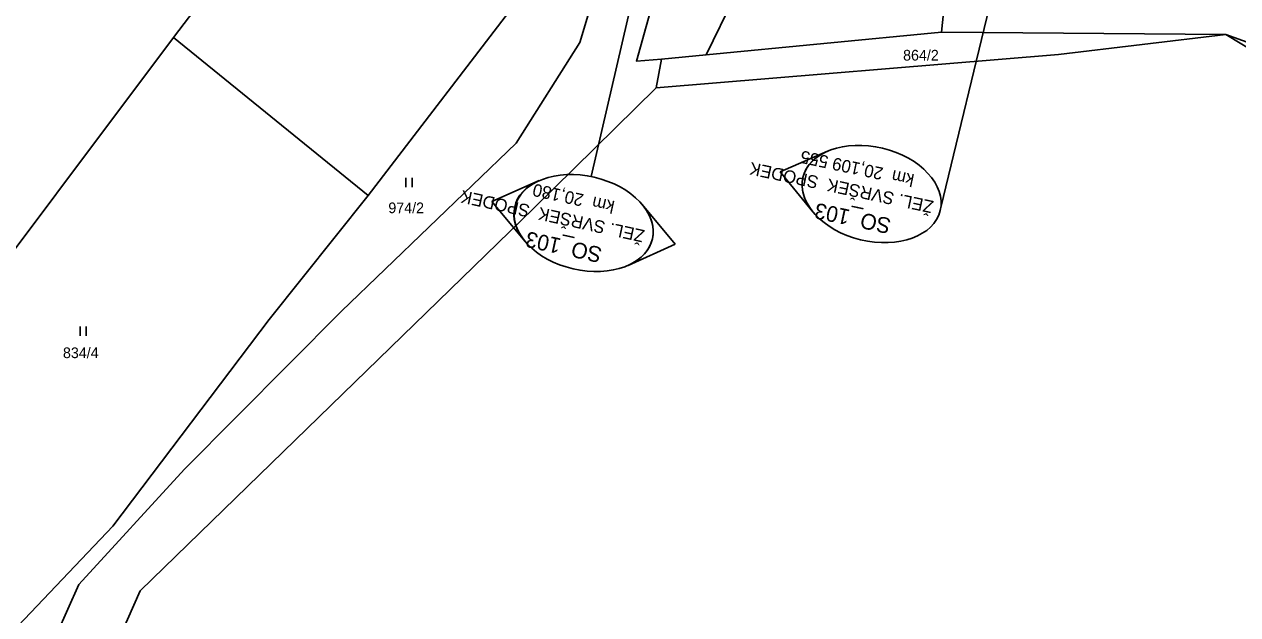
# Model space of a CAD drawing. Extents: x -7483133 to -743169, y -11317770 to -1127091.
# Drawn here: x -747701.7 to -747508.3, y -1131850 to -1131755.9 of the extents above; entities that cross this region are included whole.
import ezdxf

# ---------------------------------------------------------------- set-up
doc = ezdxf.new("R2010")
doc.units = 0
for name, color, linetype in [('_Násyp', 7, 'Continuous'), ('bublina_fialová_čára_tenká', 7, 'Continuous'), ('bublina_růžová_230_čára_tučná', 7, 'Continuous'), ('Hranice parcel', 7, 'Continuous'), ('Parcelní čísla', 7, 'Continuous'), ('Značky kultur', 7, 'Continuous')]:
    doc.layers.add(name, color=color, linetype=linetype)

msp = doc.modelspace()

# ---------------------------------------------------------------- linework, layer by layer
at = {"layer": 'bublina_fialová_čára_tenká'}
for p, q in [((-747611.38, -1131780.16), (-747594.17, -1131705.8)), ((-747555.65, -1131785.08), (-747539.65, -1131718.99))]:
    msp.add_line(p, q, dxfattribs=at)
at = {"layer": 'bublina_růžová_230_čára_tučná'}
for p, q in [((-747581.26, -1131779.44), (-747573.69, -1131776.14)), ((-747581.26, -1131779.44), (-747573.69, -1131776.14)), ((-747619.68, -1131780.79), (-747627.22, -1131784.15)), ((-747619.68, -1131780.79), (-747627.22, -1131784.15)), ((-747576.03, -1131785.82), (-747581.26, -1131779.44)), ((-747576.03, -1131785.82), (-747581.26, -1131779.44)), ((-747627.22, -1131784.15), (-747621.93, -1131790.49)), ((-747627.22, -1131784.15), (-747621.93, -1131790.49)), ((-747597.96, -1131790.97), (-747603.25, -1131784.63)), ((-747597.96, -1131790.97), (-747603.25, -1131784.63)), ((-747605.5, -1131794.33), (-747597.96, -1131790.97)), ((-747605.5, -1131794.33), (-747597.96, -1131790.97))]:
    msp.add_line(p, q, dxfattribs=at)
for centre, major_axis in [((-747566.68, -1131782.95), (10.94, -2.64)), ((-747612.57, -1131787.58), (-10.96, 2.54))]:
    msp.add_ellipse(centre, major_axis=major_axis, ratio=0.666667, dxfattribs=at)
for centre, major_axis in [((-747566.68, -1131782.95), (-10.94, 2.64)), ((-747612.6, -1131787.54), (-10.96, 2.54)), ((-747612.57, -1131787.58), (10.96, -2.54))]:
    msp.add_ellipse(centre, major_axis=major_axis, ratio=0.666473, start_param=5.557317, end_param=7.009053, dxfattribs=at)
at = {"layer": 'Hranice parcel'}
for p, q in [((-747635.51, -1131701.73), (-747677.94, -1131758.02)), ((-747551.8, -1131720.33), (-747555.53, -1131757.15)), ((-747646.92, -1131783.21), (-747603.39, -1131726.29)), ((-747593.06, -1131760.75), (-747588.32, -1131751.04)), ((-747555.53, -1131757.15), (-747593.06, -1131760.75)), ((-747555.53, -1131757.15), (-747510.21, -1131757.54)), ((-747677.94, -1131758.02), (-747646.92, -1131783.21)), ((-747600.14, -1131761.43), (-747601, -1131766.04)), ((-747593.06, -1131760.75), (-747600.14, -1131761.43))]:
    msp.add_line(p, q, dxfattribs=at)
for points in [[(-747600.14, -1131761.43), (-747604.15, -1131761.78), (-747597.33, -1131737.34), (-747594.14, -1131719.37), (-747592.13, -1131708.07)], [(-747603.39, -1131726.29), (-747613.18, -1131758.77), (-747623.35, -1131774.87), (-747651.15, -1131801.66), (-747676.19, -1131826.81), (-747693.02, -1131845.21), (-747696.56, -1131853.11), (-747694.42, -1131867.19)], [(-747510.21, -1131757.54), (-747536.87, -1131760.7), (-747601, -1131766.04)], [(-747510.21, -1131757.54), (-747496.95, -1131762.32), (-747474.01, -1131774.9), (-747459.79, -1131781.43), (-747448.86, -1131785.87)], [(-747340.05, -1131843.48), (-747375.12, -1131825.91), (-747485.07, -1131772.73), (-747510.21, -1131757.54)], [(-747677.94, -1131758.02), (-747715.35, -1131807.86), (-747754.13, -1131856.36)], [(-747601, -1131766.04), (-747620.58, -1131785.29), (-747683.25, -1131846.23), (-747689.11, -1131859.46), (-747677.59, -1131870.17)], [(-747646.92, -1131783.21), (-747662.7, -1131802.96), (-747687.62, -1131835.91), (-747713.84, -1131863.52)]]:
    msp.add_lwpolyline(points, dxfattribs=at)
at = {"layer": 'Značky kultur'}
for p, q in [((-747640.92, -1131781.88), (-747640.92, -1131780.38)), ((-747639.92, -1131781.88), (-747639.92, -1131780.38)), ((-747692.84, -1131805.57), (-747692.84, -1131804.07)), ((-747691.84, -1131805.57), (-747691.84, -1131804.07))]:
    msp.add_line(p, q, dxfattribs=at)

# ---------------------------------------------------------------- texts
at = {"layer": '_Násyp'}
for s, height, rotation, p in [('km  20,109 555', 2, 167.9379, (-747559.75, -1131779.85)), ('ŽEL. SVRŠEK  SPODEK', 2, 167.9379, (-747556.69, -1131784.09)), ('ŽEL. SVRŠEK  SPODEK', 2, 167.6146, (-747602.73, -1131788.74)), ('km  20,180', 2, 167.6146, (-747607.5, -1131784.1)), ('SO_103', 2.5, 167.9379, (-747563.43, -1131786.9)), ('SO_103', 2.5, 167.6146, (-747609.49, -1131791.52))]:
    msp.add_text(s, height=height, rotation=rotation, dxfattribs=at).set_placement(p)
at = {"layer": 'Parcelní čísla'}
for s, p in [('864/2', (-747561.66, -1131761.67)), ('974/2', (-747643.7, -1131786.01)), ('834/4', (-747695.56, -1131809.12))]:
    msp.add_text(s, height=1.7, dxfattribs=at).set_placement(p)

doc.saveas('drawing.dxf')
